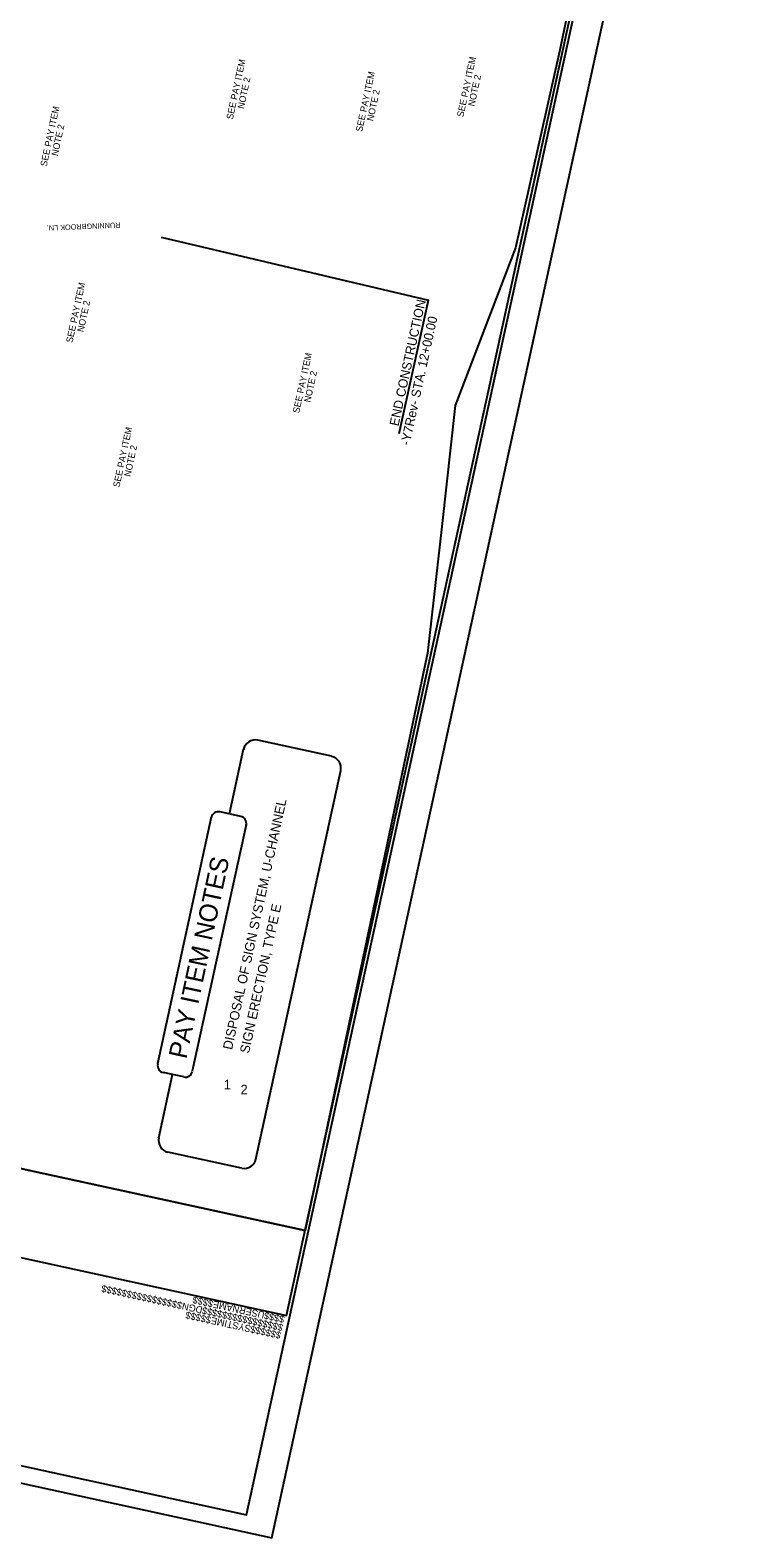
# Model space of a CAD drawing. Extents: x 1615829 to 1617263, y 900664 to 902544.
# Drawn here: x 1616720 to 1617263, y 900664 to 901807 of the extents above; entities that cross this region are included whole.
import ezdxf

# ---------------------------------------------------------------- set-up
doc = ezdxf.new("R2010")
doc.units = 0
for name, color, linetype in [('Default', 7, 'Continuous'), ('Exist PHM ROW shape', 7, 'Continuous'), ('Prop Conc Drive Radius Type', 7, 'Continuous'), ('Prop Conc Island Cover', 7, 'Continuous'), ('Prop Dimension Text', 7, 'Continuous'), ('Prop PHM Concrete Structures Shape', 7, 'Continuous'), ('Prop PHM ROW', 7, 'Continuous'), ('Prop Shade Medium', 7, 'Continuous'), ('Prop Superelevation  Arrow CELL', 7, 'Continuous'), ('Scratch_Level_2', 7, 'Continuous')]:
    doc.layers.add(name, color=color, linetype=linetype)

msp = doc.modelspace()

# ---------------------------------------------------------------- linework, layer by layer
at = {"layer": 'Exist PHM ROW shape'}
msp.add_line((1617000, 901500.9), (1617022.1, 901601.9), dxfattribs=at)
at = {"layer": 'Prop Conc Drive Radius Type'}
msp.add_lwpolyline([(1616850.4, 902379.9), (1617227.5, 902296.2), (1617121.4, 901790.4), (1617088.2, 901641.8), (1617042.4, 901522.3), (1617032.3, 901430.6), (1617021.4, 901334.4), (1616928.8, 900896.8), (1615902.8, 901120.3), (1615974.3, 901386.7), (1616087.7, 901888.9), (1616145.5, 901879.2), (1616184.1, 901827.5), (1616138.4, 901615), (1616150.6, 901618.1), (1616181.3, 901620.7), (1616299.2, 901764.2), (1616120.1, 901933.3), (1616161.3, 902112.5), (1616179.7, 902310.4), (1616356.3, 902284.9), (1616372.4, 902359)], close=True, dxfattribs=at)
at = {"layer": 'Prop Dimension Text'}
msp.add_line((1615902.8, 901120.3), (1616928.8, 900896.8), dxfattribs=at)
at = {"layer": 'Prop PHM Concrete Structures Shape'}
msp.add_lwpolyline([(1616208.8, 902521.9), (1615888.9, 901056.4), (1616914.7, 900832.5), (1617234.6, 902298)], close=True, dxfattribs=at)
at = {"layer": 'Prop PHM ROW'}
msp.add_line((1616819.6, 901649.7), (1617022.1, 901601.9), dxfattribs=at)
at = {"layer": 'Prop Shade Medium'}
msp.add_lwpolyline([(1616188, 902543.8), (1615828.8, 900898.6), (1616903.5, 900664), (1617262.7, 902309.2)], close=True, dxfattribs=at)
at = {"layer": 'Prop Superelevation  Arrow CELL'}
for p, q in [((1616871.4, 901212.6), (1616882, 901261.6)), ((1616948.8, 901256.3), (1616892.9, 901268.5)), ((1616891.4, 900951), (1616955.7, 901245.5)), ((1616880, 901210.8), (1616864.3, 901214.2)), ((1616817.8, 900967.1), (1616828.3, 901015.1)), ((1616836.8, 901013.3), (1616821.2, 901016.7)), ((1616880.6, 900944.1), (1616824.7, 900956.3))]:
    msp.add_line(p, q, dxfattribs=at)
for points in [[(1616817.1, 901023.6), (1616857.9, 901210.5)], [(1616843.4, 901017.9), (1616884.2, 901204.7)]]:
    msp.add_lwpolyline(points, dxfattribs=at)
for centre, radius, start, end in [((1616890.9, 901259.6), 9.09, 77.6862, 167.6862), ((1616946.8, 901247.4), 9.09, 347.6862, 77.6862), ((1616863.1, 901208.9), 5.45, 77.6862, 167.6862), ((1616878.8, 901205.4), 5.45, 347.6862, 77.6862), ((1616822.4, 901022), 5.45, 167.6862, 257.6862), ((1616838, 901018.6), 5.45, 257.6862, 347.6862), ((1616826.7, 900965.2), 9.09, 167.6862, 257.6862), ((1616882.6, 900953), 9.09, 257.6862, 347.6862)]:
    msp.add_arc(centre, radius, start, end, dxfattribs=at)
at = {"layer": 'Scratch_Level_2'}
msp.add_lwpolyline([(1616209, 902534.7), (1615853.6, 900906.5), (1616884.4, 900681.5), (1617239.8, 902309.6)], close=True, dxfattribs=at)

# ---------------------------------------------------------------- texts
at = {"layer": 'Default'}
for s, height, rotation, p in [('SEE PAY ITEM', 5, 77.9223, (1616873.9, 901738.6)), ('SEE PAY ITEM', 5, 77.9223, (1617048.6, 901740.5)), ('SEE PAY ITEM', 5, 77.9223, (1616971.9, 901729.3)), ('NOTE 2', 5, 77.9223, (1617057, 901748.6)), ('NOTE 2', 5, 77.9223, (1616882.3, 901746.7)), ('NOTE 2', 5, 77.9223, (1616980.3, 901737.4)), ('SEE PAY ITEM', 5, 77.9223, (1616732.9, 901703)), ('NOTE 2', 5, 77.9223, (1616741.3, 901711)), ('SEE PAY ITEM', 5, 77.9223, (1616752.4, 901569.4)), ('NOTE 2', 5, 77.9223, (1616760.8, 901577.5)), ('SEE PAY ITEM', 5, 77.9223, (1616924.2, 901516.1)), ('NOTE 2', 5, 77.9223, (1616932.7, 901524.2)), ('SEE PAY ITEM', 5, 77.9223, (1616788, 901459.8)), ('NOTE 2', 5, 77.9223, (1616796.4, 901467.9)), ('DISPOSAL OF SIGN SYSTEM, U-CHANNEL', 7.199, 77.6862, (1616873.3, 901033.5)), ('PAY ITEM NOTES', 13.866, 77.8685, (1616838.7, 901026.4)), ('SIGN ERECTION, TYPE E', 7.199, 77.6862, (1616886.2, 901030.7)), ('1', 7.2, 359.9734, (1616867.1, 901004)), ('2', 7.2, 359.9734, (1616879.8, 901000.2))]:
    msp.add_text(s, height=height, rotation=rotation, dxfattribs=at).set_placement(p)
at = {"layer": 'Exist PHM ROW shape'}
for s, p in [('END CONSTRUCTION', (1616999.4, 901506.2)), ('-Y7Rev- STA. 12+00.00', (1617007.8, 901491.6))]:
    msp.add_text(s, height=7, rotation=77.6862, dxfattribs=at).set_placement(p)
at = {"layer": 'Prop Conc Island Cover'}
msp.add_text('RUNNINGBROOK LN.', height=4, rotation=182.3975, dxfattribs=at).set_placement((1616788.7, 901661))
at = {"layer": 'Prop PHM Concrete Structures Shape'}
for s, p in [('$$$$$$$$$$$$$$$$DGN$$$$$$$$$$$$$$$$', (1616912.4, 900825.7)), ('$$$$USERNAME$$$$', (1616913.6, 900831.9)), ('$$$$$$SYSTIME$$$$$', (1616910.9, 900819.8))]:
    msp.add_text(s, height=5.25, rotation=167.6862, dxfattribs=at).set_placement(p)

doc.saveas('drawing.dxf')
